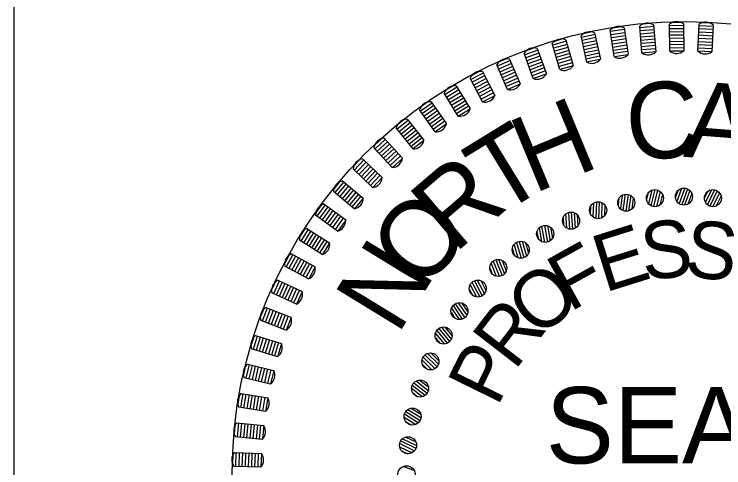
# Model space of a CAD drawing. Extents: x 2111095 to 2115970, y 670428 to 672393.
# Drawn here: x 2113050.5 to 2113107.3, y 672107.3 to 672143.6 of the extents above; entities that cross this region are included whole.
import ezdxf

# ---------------------------------------------------------------- set-up
doc = ezdxf.new("R2010")
doc.units = 0
doc.layers.add('Sheet PE Seal Cell', color=7, linetype='Continuous')
doc.layers.add('Sheet Typical CELL', color=7, linetype='Continuous')

msp = doc.modelspace()

# ---------------------------------------------------------------- linework, layer by layer
at = {"layer": 'Sheet PE Seal Cell'}
for p, q in [((2113099.049, 672142.578), (2113098.377, 672142.477)), ((2113099.284, 672142.488), (2113099.604, 672140.354)), ((2113100.72, 672140.484), (2113100.542, 672142.635)), ((2113101.665, 672142.596), (2113100.553, 672142.504)), ((2113101.426, 672142.832), (2113100.749, 672142.776)), ((2113101.654, 672142.727), (2113101.833, 672140.577)), ((2113102.955, 672140.633), (2113102.919, 672142.791)), ((2113104.038, 672142.678), (2113102.921, 672142.659)), ((2113104.042, 672142.423), (2113102.926, 672142.404)), ((2113103.815, 672142.929), (2113103.135, 672142.917)), ((2113104.035, 672142.809), (2113104.072, 672140.651)), ((2113105.195, 672140.633), (2113105.302, 672142.789)), ((2113106.41, 672142.602), (2113105.295, 672142.657)), ((2113106.205, 672142.867), (2113105.526, 672142.901)), ((2113106.417, 672142.734), (2113106.31, 672140.578)), ((2113096.304, 672139.746), (2113095.843, 672141.855)), ((2113096.962, 672141.965), (2113095.871, 672141.726)), ((2113096.695, 672142.167), (2113096.03, 672142.022)), ((2113096.934, 672142.093), (2113097.395, 672139.985)), ((2113098.5, 672140.188), (2113098.18, 672142.323)), ((2113099.303, 672142.358), (2113098.199, 672142.193)), ((2113099.341, 672142.106), (2113098.237, 672141.941)), ((2113099.379, 672141.855), (2113098.275, 672141.689)), ((2113101.686, 672142.343), (2113100.574, 672142.25)), ((2113101.707, 672142.089), (2113100.595, 672141.996)), ((2113104.046, 672142.168), (2113102.93, 672142.15)), ((2113104.05, 672141.914), (2113102.934, 672141.895)), ((2113106.372, 672141.839), (2113105.258, 672141.894)), ((2113106.385, 672142.093), (2113105.27, 672142.148)), ((2113106.398, 672142.348), (2113105.283, 672142.403)), ((2113094.652, 672141.417), (2113093.58, 672141.107)), ((2113094.372, 672141.601), (2113093.719, 672141.413)), ((2113094.616, 672141.544), (2113095.215, 672139.47)), ((2113097.016, 672141.716), (2113095.926, 672141.477)), ((2113097.071, 672141.467), (2113095.98, 672141.229)), ((2113099.417, 672141.603), (2113098.313, 672141.437)), ((2113099.454, 672141.351), (2113098.35, 672141.185)), ((2113101.728, 672141.835), (2113100.616, 672141.742)), ((2113101.749, 672141.581), (2113100.637, 672141.488)), ((2113101.77, 672141.327), (2113100.658, 672141.235)), ((2113104.055, 672141.659), (2113102.938, 672141.64)), ((2113104.059, 672141.404), (2113102.943, 672141.386)), ((2113106.347, 672141.33), (2113105.232, 672141.385)), ((2113106.36, 672141.585), (2113105.245, 672141.64)), ((2113092.383, 672140.718), (2113091.334, 672140.338)), ((2113092.092, 672140.883), (2113091.452, 672140.652)), ((2113092.339, 672140.842), (2113093.074, 672138.813)), ((2113094.142, 672139.16), (2113093.543, 672141.234)), ((2113094.723, 672141.172), (2113093.65, 672140.863)), ((2113094.794, 672140.928), (2113093.721, 672140.618)), ((2113097.125, 672141.218), (2113096.035, 672140.98)), ((2113097.18, 672140.969), (2113096.089, 672140.731)), ((2113097.234, 672140.72), (2113096.143, 672140.482)), ((2113099.492, 672141.099), (2113098.388, 672140.933)), ((2113099.53, 672140.847), (2113098.426, 672140.681)), ((2113101.792, 672141.073), (2113100.679, 672140.981)), ((2113101.813, 672140.819), (2113100.7, 672140.727)), ((2113104.063, 672141.15), (2113102.947, 672141.131)), ((2113104.067, 672140.895), (2113102.951, 672140.876)), ((2113106.322, 672140.821), (2113105.207, 672140.876)), ((2113106.335, 672141.076), (2113105.22, 672141.131)), ((2113092.024, 672138.433), (2113091.289, 672140.462)), ((2113092.47, 672140.479), (2113091.421, 672140.099)), ((2113092.557, 672140.239), (2113091.507, 672139.859)), ((2113094.864, 672140.683), (2113093.792, 672140.373)), ((2113094.935, 672140.438), (2113093.863, 672140.128)), ((2113095.006, 672140.194), (2113093.933, 672139.884)), ((2113097.288, 672140.472), (2113096.198, 672140.233)), ((2113097.343, 672140.223), (2113096.252, 672139.984)), ((2113099.568, 672140.595), (2113098.464, 672140.429)), ((2113099.592, 672140.341), (2113098.515, 672140.179)), ((2113101.82, 672140.564), (2113100.735, 672140.474)), ((2113104.058, 672140.64), (2113102.969, 672140.622)), ((2113106.296, 672140.568), (2113105.209, 672140.621)), ((2113090.166, 672139.871), (2113089.144, 672139.422)), ((2113089.864, 672140.016), (2113089.241, 672139.743)), ((2113090.268, 672139.638), (2113089.246, 672139.189)), ((2113090.113, 672139.991), (2113090.981, 672138.015)), ((2113092.644, 672140), (2113091.594, 672139.62)), ((2113092.73, 672139.76), (2113091.681, 672139.38)), ((2113095.076, 672139.949), (2113094.004, 672139.639)), ((2113095.147, 672139.704), (2113094.075, 672139.394)), ((2113097.384, 672139.971), (2113096.32, 672139.738)), ((2113087.698, 672139.004), (2113087.095, 672138.69)), ((2113089.958, 672137.567), (2113089.091, 672139.543)), ((2113090.371, 672139.404), (2113089.349, 672138.956)), ((2113090.473, 672139.171), (2113089.451, 672138.722)), ((2113092.817, 672139.521), (2113091.768, 672139.141)), ((2113092.904, 672139.281), (2113091.854, 672138.901)), ((2113092.991, 672139.042), (2113091.941, 672138.662)), ((2113095.205, 672139.456), (2113094.159, 672139.153)), ((2113087.954, 672136.566), (2113086.958, 672138.48)), ((2113088.009, 672138.879), (2113087.019, 672138.364)), ((2113088.127, 672138.653), (2113087.137, 672138.138)), ((2113087.949, 672138.995), (2113088.945, 672137.081)), ((2113090.575, 672138.938), (2113089.553, 672138.489)), ((2113090.678, 672138.705), (2113089.656, 672138.256)), ((2113090.78, 672138.471), (2113089.758, 672138.023)), ((2113093.064, 672138.798), (2113092.041, 672138.427)), ((2113088.244, 672138.427), (2113087.254, 672137.912)), ((2113088.362, 672138.201), (2113087.372, 672137.686)), ((2113088.48, 672137.975), (2113087.489, 672137.46)), ((2113090.883, 672138.238), (2113089.86, 672137.79)), ((2113090.972, 672137.999), (2113089.976, 672137.562)), ((2113085.923, 672137.746), (2113084.969, 672137.167)), ((2113085.604, 672137.851), (2113085.023, 672137.498)), ((2113086.055, 672137.529), (2113085.101, 672136.949)), ((2113086.187, 672137.311), (2113085.233, 672136.731)), ((2113085.855, 672137.859), (2113086.975, 672136.014)), ((2113088.597, 672137.749), (2113087.607, 672137.234)), ((2113088.715, 672137.523), (2113087.724, 672137.008)), ((2113088.832, 672137.297), (2113087.842, 672136.782)), ((2113086.021, 672135.435), (2113084.901, 672137.279)), ((2113086.32, 672137.093), (2113085.366, 672136.514)), ((2113086.452, 672136.876), (2113085.498, 672136.296)), ((2113088.938, 672137.065), (2113087.972, 672136.562)), ((2113083.916, 672136.479), (2113083.002, 672135.837)), ((2113083.591, 672136.562), (2113083.034, 672136.171)), ((2113084.062, 672136.27), (2113083.149, 672135.629)), ((2113083.84, 672136.586), (2113085.08, 672134.82)), ((2113086.584, 672136.658), (2113085.63, 672136.078)), ((2113086.716, 672136.44), (2113085.762, 672135.861)), ((2113086.849, 672136.222), (2113085.895, 672135.643)), ((2113084.167, 672134.178), (2113082.927, 672135.945)), ((2113084.209, 672136.062), (2113083.295, 672135.42)), ((2113084.355, 672135.853), (2113083.441, 672135.212)), ((2113084.501, 672135.645), (2113083.588, 672135.003)), ((2113086.969, 672135.998), (2113086.039, 672135.432)), ((2113081.997, 672135.081), (2113081.128, 672134.381)), ((2113081.667, 672135.142), (2113081.138, 672134.716)), ((2113081.915, 672135.183), (2113083.269, 672133.503)), ((2113084.648, 672135.436), (2113083.734, 672134.795)), ((2113084.794, 672135.228), (2113083.88, 672134.586)), ((2113082.399, 672132.802), (2113081.045, 672134.483)), ((2113082.157, 672134.882), (2113081.288, 672134.182)), ((2113082.317, 672134.684), (2113081.447, 672133.984)), ((2113082.477, 672134.486), (2113081.607, 672133.785)), ((2113084.94, 672135.019), (2113084.027, 672134.378)), ((2113085.075, 672134.803), (2113084.184, 672134.177)), ((2113082.636, 672134.287), (2113081.767, 672133.587)), ((2113082.796, 672134.089), (2113081.927, 672133.389)), ((2113082.956, 672133.891), (2113082.087, 672133.19)), ((2113079.842, 672133.599), (2113079.342, 672133.138)), ((2113080.175, 672133.559), (2113079.354, 672132.803)), ((2113080.347, 672133.372), (2113079.526, 672132.616)), ((2113080.086, 672133.656), (2113081.548, 672132.069)), ((2113083.116, 672133.692), (2113082.247, 672132.992)), ((2113083.265, 672133.485), (2113082.417, 672132.802)), ((2113080.727, 672131.312), (2113079.265, 672132.9)), ((2113080.52, 672133.185), (2113079.699, 672132.428)), ((2113080.693, 672132.997), (2113079.872, 672132.241)), ((2113080.865, 672132.81), (2113080.044, 672132.054)), ((2113081.038, 672132.623), (2113080.217, 672131.866)), ((2113081.21, 672132.435), (2113080.389, 672131.679)), ((2113081.383, 672132.248), (2113080.562, 672131.492)), ((2113078.122, 672131.938), (2113077.654, 672131.446)), ((2113078.457, 672131.921), (2113077.688, 672131.112)), ((2113078.642, 672131.745), (2113077.872, 672130.936)), ((2113078.362, 672132.011), (2113079.926, 672130.524)), ((2113081.545, 672132.051), (2113080.745, 672131.314)), ((2113079.156, 672129.715), (2113077.593, 672131.203)), ((2113078.826, 672131.57), (2113078.057, 672130.761)), ((2113079.011, 672131.394), (2113078.242, 672130.585)), ((2113079.196, 672131.219), (2113078.426, 672130.41)), ((2113079.38, 672131.043), (2113078.611, 672130.234)), ((2113079.565, 672130.868), (2113078.795, 672130.059)), ((2113079.749, 672130.692), (2113078.98, 672129.883)), ((2113079.924, 672130.506), (2113079.174, 672129.718)), ((2113076.516, 672130.168), (2113076.081, 672129.645)), ((2113076.852, 672130.172), (2113076.137, 672129.314)), ((2113077.047, 672130.009), (2113076.333, 672129.151)), ((2113076.751, 672130.256), (2113078.409, 672128.876)), ((2113077.695, 672128.018), (2113076.036, 672129.398)), ((2113077.243, 672129.846), (2113076.529, 672128.988)), ((2113077.439, 672129.683), (2113076.725, 672128.825)), ((2113077.635, 672129.52), (2113076.921, 672128.662)), ((2113077.83, 672129.357), (2113077.116, 672128.5)), ((2113101.505, 672129.498), (2113101.237, 672128.424)), ((2113101.75, 672129.546), (2113101.432, 672128.266)), ((2113101.975, 672129.509), (2113101.647, 672128.193)), ((2113102.181, 672129.396), (2113101.882, 672128.197)), ((2113103.585, 672129.458), (2113103.397, 672128.942)), ((2113103.894, 672129.643), (2113103.515, 672128.602)), ((2113104.143, 672129.665), (2113103.692, 672128.426)), ((2113104.363, 672129.605), (2113103.899, 672128.33)), ((2113104.555, 672129.471), (2113104.133, 672128.309)), ((2113105.958, 672129.386), (2113105.718, 672128.892)), ((2113106.285, 672129.537), (2113105.799, 672128.542)), ((2113106.535, 672129.533), (2113105.957, 672128.348)), ((2113106.747, 672129.451), (2113106.153, 672128.231)), ((2113078.026, 672129.194), (2113077.312, 672128.337)), ((2113078.222, 672129.032), (2113077.508, 672128.174)), ((2113078.409, 672128.858), (2113077.712, 672128.021)), ((2113098.88, 672128.86), (2113098.804, 672128.316)), ((2113099.144, 672129.104), (2113098.99, 672128.008)), ((2113099.383, 672129.177), (2113099.2, 672127.872)), ((2113099.611, 672129.165), (2113099.422, 672127.821)), ((2113099.827, 672129.074), (2113099.655, 672127.849)), ((2113100.028, 672128.874), (2113099.903, 672127.985)), ((2113101.217, 672129.282), (2113101.084, 672128.749)), ((2113102.36, 672129.177), (2113102.143, 672128.306)), ((2113104.711, 672129.234), (2113104.404, 672128.391)), ((2113106.925, 672129.297), (2113106.383, 672128.186)), ((2113107.054, 672129.046), (2113106.661, 672128.239)), ((2113075.031, 672128.295), (2113074.631, 672127.744)), ((2113075.365, 672128.321), (2113074.709, 672127.418)), ((2113075.259, 672128.399), (2113077.005, 672127.131)), ((2113096.837, 672128.466), (2113096.799, 672127.359)), ((2113097.068, 672128.564), (2113097.022, 672127.246)), ((2113097.295, 672128.574), (2113097.248, 672127.219)), ((2113097.52, 672128.507), (2113097.477, 672127.271)), ((2113097.741, 672128.33), (2113097.709, 672127.432)), ((2113075.571, 672128.172), (2113074.915, 672127.269)), ((2113075.777, 672128.022), (2113075.121, 672127.119)), ((2113075.983, 672127.872), (2113075.327, 672126.969)), ((2113076.19, 672127.723), (2113075.534, 672126.82)), ((2113094.829, 672127.711), (2113094.921, 672126.396)), ((2113095.054, 672127.746), (2113095.149, 672126.393)), ((2113095.284, 672127.702), (2113095.371, 672126.468)), ((2113096.601, 672128.195), (2113096.582, 672127.646)), ((2113076.349, 672126.227), (2113074.603, 672127.495)), ((2113076.396, 672127.573), (2113075.74, 672126.67)), ((2113076.602, 672127.423), (2113075.946, 672126.52)), ((2113076.808, 672127.274), (2113076.152, 672126.371)), ((2113077.006, 672127.113), (2113076.366, 672126.232)), ((2113094.403, 672127.296), (2113094.442, 672126.748)), ((2113094.61, 672127.59), (2113094.688, 672126.485)), ((2113095.523, 672127.549), (2113095.585, 672126.653)), ((2113092.692, 672126.629), (2113092.921, 672125.331)), ((2113092.912, 672126.687), (2113093.148, 672125.352)), ((2113093.146, 672126.668), (2113093.361, 672125.45)), ((2113093.398, 672126.54), (2113093.555, 672125.656)), ((2113073.672, 672126.328), (2113073.31, 672125.752)), ((2113074.004, 672126.376), (2113073.409, 672125.432)), ((2113074.22, 672126.241), (2113073.625, 672125.296)), ((2113074.435, 672126.105), (2113073.84, 672125.16)), ((2113073.893, 672126.447), (2113075.719, 672125.297)), ((2113074.651, 672125.969), (2113074.056, 672125.025)), ((2113092.312, 672126.171), (2113092.407, 672125.631)), ((2113092.487, 672126.486), (2113092.679, 672125.395)), ((2113075.124, 672124.352), (2113073.298, 672125.502)), ((2113074.866, 672125.834), (2113074.271, 672124.889)), ((2113075.082, 672125.698), (2113074.487, 672124.753)), ((2113075.297, 672125.562), (2113074.703, 672124.617)), ((2113075.513, 672125.426), (2113074.918, 672124.482)), ((2113090.892, 672125.41), (2113091.266, 672124.107)), ((2113091.127, 672125.415), (2113091.468, 672124.227)), ((2113075.721, 672125.279), (2113075.141, 672124.358)), ((2113090.349, 672124.835), (2113090.501, 672124.307)), ((2113090.49, 672125.166), (2113090.796, 672124.101)), ((2113090.679, 672125.33), (2113091.043, 672124.062)), ((2113091.391, 672125.315), (2113091.639, 672124.452)), ((2113072.447, 672124.275), (2113072.123, 672123.677)), ((2113072.775, 672124.346), (2113072.244, 672123.364)), ((2113072.659, 672124.408), (2113074.557, 672123.382)), ((2113072.999, 672124.225), (2113072.468, 672123.243)), ((2113073.223, 672124.103), (2113072.692, 672123.122)), ((2113073.447, 672123.982), (2113072.916, 672123)), ((2113073.671, 672123.861), (2113073.14, 672122.879)), ((2113073.895, 672123.74), (2113073.364, 672122.758)), ((2113088.813, 672123.827), (2113089.308, 672122.605)), ((2113089.017, 672123.93), (2113089.525, 672122.672)), ((2113089.249, 672123.959), (2113089.713, 672122.813)), ((2113089.523, 672123.887), (2113089.86, 672123.055)), ((2113074.026, 672122.4), (2113072.128, 672123.426)), ((2113074.119, 672123.619), (2113073.588, 672122.637)), ((2113074.343, 672123.497), (2113073.812, 672122.516)), ((2113074.56, 672123.364), (2113074.043, 672122.407)), ((2113088.537, 672123.301), (2113088.743, 672122.791)), ((2113088.643, 672123.644), (2113089.058, 672122.618)), ((2113071.36, 672122.146), (2113071.076, 672121.528)), ((2113071.682, 672122.238), (2113071.217, 672121.223)), ((2113071.914, 672122.132), (2113071.449, 672121.117)), ((2113071.562, 672122.293), (2113073.524, 672121.394)), ((2113072.145, 672122.026), (2113071.68, 672121.011)), ((2113087.115, 672122.138), (2113087.734, 672120.974)), ((2113087.306, 672122.261), (2113087.943, 672121.064)), ((2113087.535, 672122.315), (2113088.116, 672121.223)), ((2113087.815, 672122.272), (2113088.236, 672121.479)), ((2113072.377, 672121.92), (2113071.912, 672120.905)), ((2113072.608, 672121.814), (2113072.143, 672120.799)), ((2113072.84, 672121.708), (2113072.375, 672120.693)), ((2113073.071, 672121.602), (2113072.606, 672120.587)), ((2113073.303, 672121.495), (2113072.838, 672120.481)), ((2113086.895, 672121.585), (2113087.153, 672121.1)), ((2113086.964, 672121.938), (2113087.484, 672120.96)), ((2113073.059, 672120.379), (2113071.097, 672121.278)), ((2113073.529, 672121.377), (2113073.075, 672120.387)), ((2113085.602, 672120.28), (2113086.34, 672119.187)), ((2113085.78, 672120.423), (2113086.539, 672119.298)), ((2113086.002, 672120.5), (2113086.693, 672119.475)), ((2113086.284, 672120.486), (2113086.786, 672119.742)), ((2113070.415, 672119.95), (2113070.174, 672119.314)), ((2113070.731, 672120.063), (2113070.334, 672119.02)), ((2113070.969, 672119.973), (2113070.572, 672118.929)), ((2113070.608, 672120.11), (2113072.625, 672119.343)), ((2113071.207, 672119.882), (2113070.81, 672118.839)), ((2113071.445, 672119.791), (2113071.048, 672118.748)), ((2113071.683, 672119.701), (2113071.287, 672118.657)), ((2113085.441, 672119.708), (2113085.749, 672119.252)), ((2113085.473, 672120.066), (2113086.093, 672119.148)), ((2113071.922, 672119.61), (2113071.525, 672118.567)), ((2113072.16, 672119.52), (2113071.763, 672118.476)), ((2113072.398, 672119.429), (2113072.001, 672118.386)), ((2113072.631, 672119.326), (2113072.244, 672118.308)), ((2113072.228, 672118.299), (2113070.211, 672119.067)), ((2113084.949, 672118.551), (2113085.526, 672117.863)), ((2113084.187, 672118.048), (2113084.898, 672117.2)), ((2113084.292, 672118.275), (2113085.14, 672117.265)), ((2113084.454, 672118.435), (2113085.326, 672117.396)), ((2113084.666, 672118.535), (2113085.461, 672117.588)), ((2113069.619, 672117.696), (2113069.419, 672117.046)), ((2113069.926, 672117.83), (2113069.599, 672116.763)), ((2113069.8, 672117.868), (2113071.864, 672117.236)), ((2113070.17, 672117.755), (2113069.843, 672116.688)), ((2113070.413, 672117.681), (2113070.086, 672116.613)), ((2113070.657, 672117.606), (2113070.33, 672116.539)), ((2113070.9, 672117.531), (2113070.573, 672116.464)), ((2113071.144, 672117.457), (2113070.817, 672116.389)), ((2113084.192, 672117.688), (2113084.545, 672117.268)), ((2113071.387, 672117.382), (2113071.06, 672116.315)), ((2113071.631, 672117.307), (2113071.304, 672116.24)), ((2113071.87, 672117.22), (2113071.551, 672116.179)), ((2113071.537, 672116.169), (2113069.473, 672116.801)), ((2113083.343, 672116.319), (2113084.319, 672115.377)), ((2113083.544, 672116.441), (2113084.433, 672115.582)), ((2113083.823, 672116.487), (2113084.469, 672115.863)), ((2113083.118, 672115.906), (2113083.914, 672115.137)), ((2113083.199, 672116.143), (2113084.148, 672115.227)), ((2113068.972, 672115.394), (2113068.817, 672114.733)), ((2113069.27, 672115.548), (2113069.015, 672114.462)), ((2113069.142, 672115.578), (2113071.243, 672115.084)), ((2113069.518, 672115.49), (2113069.262, 672114.403)), ((2113069.766, 672115.432), (2113069.51, 672114.345)), ((2113070.014, 672115.373), (2113069.758, 672114.287)), ((2113070.262, 672115.315), (2113070.006, 672114.228)), ((2113070.51, 672115.256), (2113070.254, 672114.17)), ((2113070.758, 672115.198), (2113070.502, 672114.111)), ((2113083.161, 672115.549), (2113083.556, 672115.168)), ((2113071.006, 672115.14), (2113070.75, 672114.053)), ((2113071.251, 672115.068), (2113071.001, 672114.008)), ((2113070.987, 672113.997), (2113068.887, 672114.492)), ((2113082.459, 672114.099), (2113083.528, 672113.265)), ((2113082.646, 672114.241), (2113083.621, 672113.48)), ((2113082.919, 672114.316), (2113083.627, 672113.763)), ((2113082.278, 672113.665), (2113083.151, 672112.984)), ((2113082.335, 672113.909), (2113083.374, 672113.097)), ((2113068.48, 672113.055), (2113068.368, 672112.384)), ((2113068.767, 672113.228), (2113068.583, 672112.127)), ((2113068.637, 672113.25), (2113070.766, 672112.895)), ((2113069.018, 672113.187), (2113068.835, 672112.085)), ((2113069.269, 672113.145), (2113069.086, 672112.044)), ((2113069.521, 672113.103), (2113069.337, 672112.002)), ((2113069.772, 672113.061), (2113069.588, 672111.96)), ((2113070.023, 672113.019), (2113069.84, 672111.918)), ((2113070.274, 672112.977), (2113070.091, 672111.876)), ((2113070.526, 672112.935), (2113070.342, 672111.834)), ((2113070.775, 672112.88), (2113070.596, 672111.806)), ((2113082.359, 672113.315), (2113082.792, 672112.976)), ((2113070.582, 672111.794), (2113068.454, 672112.149)), ((2113081.813, 672111.799), (2113082.963, 672111.081)), ((2113081.984, 672111.96), (2113083.032, 672111.305)), ((2113082.248, 672112.062), (2113083.009, 672111.587)), ((2113081.678, 672111.348), (2113082.617, 672110.762)), ((2113081.709, 672111.597), (2113082.827, 672110.898)), ((2113068.143, 672110.688), (2113068.076, 672110.012)), ((2113068.287, 672110.893), (2113070.435, 672110.68)), ((2113068.418, 672110.88), (2113068.308, 672109.77)), ((2113068.671, 672110.855), (2113068.561, 672109.744)), ((2113068.925, 672110.83), (2113068.814, 672109.719)), ((2113069.178, 672110.805), (2113069.068, 672109.694)), ((2113069.432, 672110.78), (2113069.321, 672109.669)), ((2113069.685, 672110.755), (2113069.575, 672109.644)), ((2113069.939, 672110.729), (2113069.828, 672109.619)), ((2113070.192, 672110.704), (2113070.082, 672109.593)), ((2113070.444, 672110.665), (2113070.337, 672109.582)), ((2113081.794, 672111.008), (2113082.26, 672110.717)), ((2113070.324, 672109.569), (2113068.177, 672109.783)), ((2113081.563, 672109.621), (2113082.675, 672109.08)), ((2113081.815, 672109.751), (2113082.622, 672109.358)), ((2113081.323, 672108.981), (2113082.318, 672108.496)), ((2113081.327, 672109.232), (2113082.513, 672108.654)), ((2113081.41, 672109.444), (2113082.629, 672108.85)), ((2113068.093, 672108.519), (2113070.25, 672108.448)), ((2113068.225, 672108.514), (2113068.188, 672107.399)), ((2113068.479, 672108.506), (2113068.443, 672107.39)), ((2113068.734, 672108.498), (2113068.697, 672107.382)), ((2113068.988, 672108.489), (2113068.952, 672107.374)), ((2113069.243, 672108.481), (2113069.206, 672107.365)), ((2113069.498, 672108.473), (2113069.461, 672107.357)), ((2113069.752, 672108.464), (2113069.716, 672107.348)), ((2113070.007, 672108.456), (2113069.97, 672107.34)), ((2113070.261, 672108.434), (2113070.225, 672107.346)), ((2113081.474, 672108.655), (2113081.968, 672108.414)), ((2113067.963, 672108.305), (2113067.941, 672107.625)), ((2113070.214, 672107.332), (2113068.057, 672107.403)), ((2113081.626, 672107.407), (2113082.47, 672107.101))]:
    msp.add_line(p, q, dxfattribs=at)
for centre, radius in [((2113104.13, 672106.779), 36.215), ((2113101.755, 672128.865), 0.681), ((2113104.076, 672128.987), 0.681), ((2113106.398, 672128.866), 0.681), ((2113099.459, 672128.501), 0.681), ((2113097.214, 672127.899), 0.681), ((2113095.044, 672127.065), 0.681), ((2113092.973, 672126.009), 0.681), ((2113091.023, 672124.743), 0.681), ((2113089.217, 672123.279), 0.681), ((2113087.574, 672121.635), 0.681), ((2113086.111, 672119.828), 0.681), ((2113084.846, 672117.878), 0.681), ((2113083.791, 672115.807), 0.681), ((2113082.958, 672113.636), 0.681), ((2113082.357, 672111.391), 0.681), ((2113081.994, 672109.095), 0.681), ((2113081.873, 672106.773), 0.681)]:
    msp.add_circle(centre, radius, dxfattribs=at)
for centre, radius, start, end in [((2113103.49, 672142.067), 0.922, 53.6912, 128.2321), ((2113098.841, 672141.68), 0.922, 61.2701, 135.8111), ((2113101.159, 672141.95), 0.922, 57.4806, 132.0216), ((2113105.823, 672142.029), 0.922, 49.9017, 124.4427), ((2113096.545, 672141.257), 0.922, 65.0596, 139.6006), ((2113094.283, 672140.684), 0.922, 68.8491, 143.39), ((2113092.064, 672139.962), 0.922, 72.6385, 147.1795), ((2113098.952, 672140.941), 0.878, 239.0439, 318.0374), ((2113101.221, 672141.205), 0.878, 235.2544, 314.2479), ((2113103.502, 672141.319), 0.878, 231.4649, 310.4584), ((2113105.786, 672141.282), 0.878, 227.6754, 306.6689), ((2113089.897, 672139.095), 0.922, 76.428, 150.969), ((2113096.705, 672140.527), 0.878, 242.8333, 321.8268), ((2113087.792, 672138.087), 0.922, 80.2175, 154.7585), ((2113094.491, 672139.966), 0.878, 246.6228, 325.6163), ((2113092.318, 672139.259), 0.878, 250.4123, 329.4058), ((2113085.758, 672136.942), 0.922, 84.007, 158.5479), ((2113090.197, 672138.411), 0.878, 254.2018, 333.1952), ((2113088.137, 672137.424), 0.878, 257.9912, 336.9847), ((2113083.805, 672135.665), 0.922, 87.7964, 162.3374), ((2113086.147, 672136.303), 0.878, 261.7807, 340.7742), ((2113081.94, 672134.262), 0.922, 91.5859, 166.1269), ((2113084.234, 672135.053), 0.878, 265.5702, 344.5637), ((2113080.172, 672132.738), 0.922, 95.3754, 169.9164), ((2113082.409, 672133.68), 0.878, 269.3596, 348.3531), ((2113078.509, 672131.102), 0.922, 99.1649, 173.7058), ((2113080.679, 672132.189), 0.878, 273.1491, 352.1426), ((2113079.05, 672130.586), 0.878, 276.9386, 355.9321), ((2113076.957, 672129.358), 0.922, 102.9543, 177.4953), ((2113077.532, 672128.88), 0.878, 280.7281, 359.7216), ((2113075.524, 672127.516), 0.922, 106.7438, 181.2848), ((2113076.129, 672127.077), 0.878, 284.5175, 3.511), ((2113074.216, 672125.583), 0.922, 110.5333, 185.0742), ((2113074.849, 672125.185), 0.878, 288.307, 7.3005), ((2113073.039, 672123.568), 0.922, 114.3228, 188.8637), ((2113073.696, 672123.213), 0.878, 292.0965, 11.09), ((2113071.997, 672121.48), 0.922, 118.1122, 192.6532), ((2113072.676, 672121.169), 0.878, 295.886, 14.8795), ((2113071.095, 672119.327), 0.922, 121.9017, 196.4427), ((2113071.794, 672119.062), 0.878, 299.6754, 18.6689), ((2113070.338, 672117.12), 0.922, 125.6912, 200.2321), ((2113071.053, 672116.901), 0.878, 303.4649, 22.4584), ((2113069.728, 672114.867), 0.922, 129.4806, 204.0216), ((2113070.456, 672114.696), 0.878, 307.2544, 26.2479), ((2113069.269, 672112.579), 0.922, 133.2701, 207.8111), ((2113070.006, 672112.456), 0.878, 311.0439, 30.0374), ((2113068.962, 672110.265), 0.922, 137.0596, 211.6006), ((2113069.706, 672110.192), 0.878, 314.8333, 33.8268), ((2113068.808, 672107.937), 0.922, 140.8491, 215.39), ((2113069.555, 672107.912), 0.878, 318.6228, 37.6163)]:
    msp.add_arc(centre, radius, start, end, dxfattribs=at)
at = {"layer": 'Sheet Typical CELL'}
msp.add_lwpolyline([(2113050.473, 672165.983), (2113150.523, 672165.983), (2113150.523, 672053.483), (2113050.473, 672053.483)], close=True, dxfattribs=at)

# ---------------------------------------------------------------- texts
at = {"layer": 'Sheet PE Seal Cell'}
for s, height, rotation, p in [('C', 6.113, 4.5143, (2113099.651, 672131.828)), ('A', 6.113, 355.5143, (2113103.973, 672132.185)), ('H', 6.113, 22.5143, (2113092.02, 672129.188)), ('T', 6.113, 31.5143, (2113089.258, 672127.391)), ('R', 6.113, 40.5143, (2113085.685, 672124.364)), ('O', 6.113, 49.5143, (2113083.161, 672121.27)), ('S', 4.585, 5.8207, (2113100.855, 672122.284)), ('S', 4.585, 354.2078, (2113104.043, 672122.616)), ('E', 4.585, 17.4336, (2113097.722, 672121.293)), ('N', 6.113, 58.5143, (2113081.151, 672117.818)), ('F', 4.585, 29.0465, (2113094.93, 672119.716)), ('O', 4.585, 40.6595, (2113092.451, 672117.555)), ('R', 4.585, 52.2724, (2113090.52, 672114.993)), ('P', 4.585, 63.8853, (2113089.144, 672112.095)), ('SEAL', 6.1134, 0.0143, (2113093.019, 672107.642))]:
    msp.add_text(s, height=height, rotation=rotation, dxfattribs=at).set_placement(p)

doc.saveas('drawing.dxf')
